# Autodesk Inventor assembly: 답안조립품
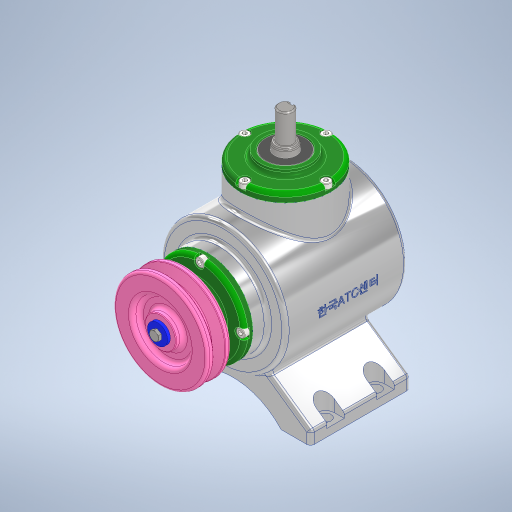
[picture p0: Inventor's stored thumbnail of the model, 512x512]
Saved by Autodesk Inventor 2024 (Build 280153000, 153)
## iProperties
Created: 2023-08
Part Number: 답안조립품
Document SubType Name: Assembly
Designer: Owner
Author: Owner
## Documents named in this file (17)
- C:\Users\Owner\Desktop\730813V1001\답안조립품.iam
- C:\Users\Owner\Desktop\730813V1001\본체.ipt
- C:\Users\Owner\Desktop\730813V1001\V-벨트풀리.ipt
- C:\Users\Owner\Desktop\730813V1001\메인 베벨기어.ipt
- C:\Users\Owner\Desktop\730813V1001\메인 축.ipt
- 메인 축.ipt
- C:\Users\Owner\Desktop\730813V1001\베어링 6203.ipt
- C:\Users\Owner\Desktop\730813V1001\볼트 M4 x 10.ipt
- C:\Users\Owner\Desktop\730813V1001\서브 베벨기어.ipt
- C:\Users\Owner\Desktop\730813V1001\서브 축.ipt
- 서브 축.ipt
- C:\Users\Owner\Desktop\730813V1001\오일실 17 x 32 x 8.ipt
- C:\Users\Owner\Desktop\730813V1001\와셔 4 x 16.ipt
- C:\Users\Owner\Desktop\730813V1001\육각볼트 M4 x 8.ipt
- C:\Users\Owner\Desktop\730813V1001\커버.ipt
- C:\Users\Owner\Desktop\730813V1001\키 4 x 4 x 14.ipt
- C:\Users\Owner\Desktop\730813V1001\키 5 x 5 x 14.ipt
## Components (1 placed, 1 different names)
1. V-벨트풀리:1
